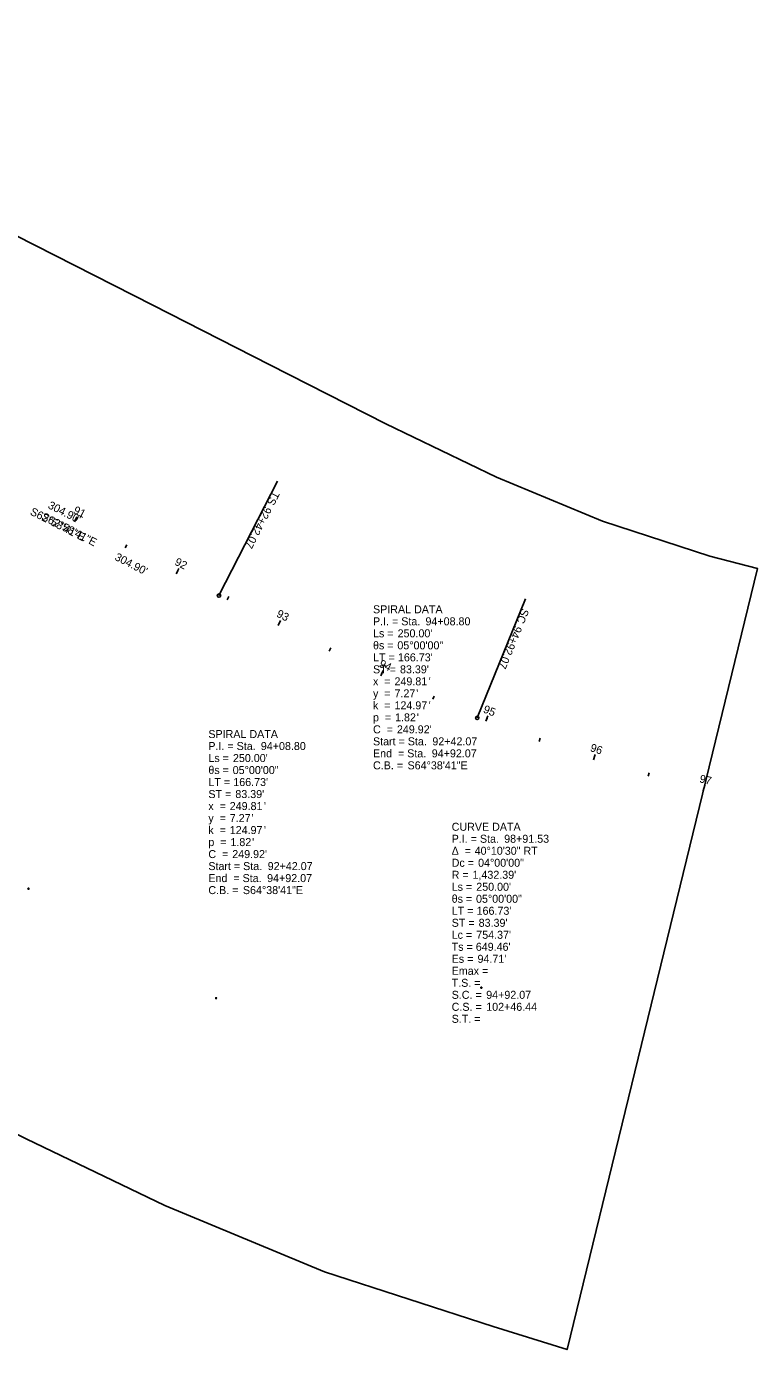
# Model space of a CAD drawing. Extents: x 1999328 to 2003366, y 252318 to 253988.
# Drawn here: x 2001707 to 2002347, y 252318 to 253475 of the extents above; entities that cross this region are included whole.
import ezdxf

# ---------------------------------------------------------------- set-up
doc = ezdxf.new("R2010")
doc.units = 0
for name, color, linetype in [('GE_P_Alignment_500_Stations', 7, 'Continuous'), ('GE_X_Alignment_100_Stations', 7, 'Continuous'), ('RW_X_Esmt_CH', 7, 'Continuous'), ('SC_Scratch3', 7, 'Continuous'), ('SV_X_Mon_Cells_Found', 7, 'Continuous'), ('TX_P_50', 7, 'Continuous'), ('TX_X_20', 7, 'Continuous'), ('TX_X_50', 7, 'Continuous')]:
    doc.layers.add(name, color=color, linetype=linetype)

msp = doc.modelspace()

# ---------------------------------------------------------------- linework, layer by layer
at = {"layer": 'GE_P_Alignment_500_Stations'}
for p, q in [((2001875.8, 252977.6), (2001927, 253077.8)), ((2001749.3, 253042.2), (2001751.6, 253046.6)), ((2001793.8, 253019.5), (2001795.2, 253022.1)), ((2001838.4, 252996.7), (2001840.6, 253001.2)), ((2001882.9, 252974), (2001884.3, 252976.7)), ((2002101.7, 252870.6), (2002143.9, 252974.9)), ((2001927.5, 252951.4), (2001929.7, 252955.9)), ((2001972.3, 252929.1), (2001973.6, 252931.8)), ((2002017.4, 252907.5), (2002019.5, 252912)), ((2002062.9, 252886.9), (2002064.1, 252889.7)), ((2002109.1, 252867.7), (2002110.9, 252872.3)), ((2002155.8, 252850), (2002156.8, 252852.8)), ((2002203.2, 252833.9), (2002204.7, 252838.7)), ((2002251.1, 252819.6), (2002251.9, 252822.5)), ((2002299.4, 252806.9), (2002300.6, 252811.7))]:
    msp.add_line(p, q, dxfattribs=at)
for centre in [(2001875.8, 252977.6), (2002101.7, 252870.6)]:
    msp.add_circle(centre, 1.5, dxfattribs=at)
at = {"layer": 'RW_X_Esmt_CH'}
msp.add_lwpolyline([(2001251, 253475.4), (2001057.7, 252727.4), (2001128.3, 252693.2), (2001227.4, 252644.1), (2001300.1, 252709.6), (2001397.4, 252660.4), (2001499.9, 252608.1), (2001602.3, 252555.9), (2001707.3, 252502.5), (2001828.3, 252444.1), (2001968.2, 252386.2), (2002115.7, 252338.2), (2002180.2, 252318.1), (2002346.8, 253001.2), (2002305.2, 253012.1), (2002211.1, 253042.7), (2002118.4, 253081.1), (2002021.8, 253127.8), (2001920.3, 253179.5), (2001817.9, 253231.7), (2001715.4, 253283.9), (2001610.7, 253336.9), (2001497.9, 253389.8), (2001376.4, 253437.5)], close=True, dxfattribs=at)
at = {"layer": 'SV_X_Mon_Cells_Found'}
for p, q in [((2001875.8, 252977.6), (2001927, 253077.8)), ((2002101.7, 252870.6), (2002143.9, 252974.9)), ((2002109.1, 252867.7), (2002110.2, 252870.4))]:
    msp.add_line(p, q, dxfattribs=at)
for centre in [(2001875.8, 252977.6), (2002101.7, 252870.6)]:
    msp.add_circle(centre, 1.5, dxfattribs=at)
at = {"layer": 'TX_P_50'}
for p, q in [((2001875.8, 252977.6), (2001927, 253077.8)), ((2001749.3, 253042.2), (2001750.7, 253044.8)), ((2001838.4, 252996.7), (2001839.7, 252999.4)), ((2002101.7, 252870.6), (2002143.9, 252974.9)), ((2001927.5, 252951.4), (2001928.8, 252954.1)), ((2002017.4, 252907.5), (2002018.6, 252910.2)), ((2002109.1, 252867.7), (2002110.9, 252872.3)), ((2002203.2, 252833.9), (2002204.1, 252836.8)), ((2002299.4, 252806.9), (2002300.1, 252809.8))]:
    msp.add_line(p, q, dxfattribs=at)
for centre in [(2001875.8, 252977.6), (2002101.7, 252870.6)]:
    msp.add_circle(centre, 1.5, dxfattribs=at)
at = {"layer": 'TX_X_20'}
for centre in [(2001709.2, 252721.3), (2001709.2, 252721.3), (2002105.2, 252634.6), (2002105.2, 252634.6), (2001873.3, 252625.5), (2001873.3, 252625.5)]:
    msp.add_circle(centre, 0.5, dxfattribs=at)

# ---------------------------------------------------------------- texts
at = {"layer": 'GE_P_Alignment_500_Stations'}
for s, rotation, p in [('TS', 242.9781, (2001922.9, 253069.6)), ('S62°58\'41"E', 332.9781, (2001719.8, 253044.4)), ('91', 332.9781, (2001747.7, 253050.1)), ('92+42.07', 242.9781, (2001916, 253056.1)), ("304.90'", 332.9781, (2001784, 253009.1)), ('92', 332.9781, (2001836.4, 253004.9)), ('93', 333.2466, (2001925.5, 252959.5)), ('SC', 247.9781, (2002140.7, 252966.9)), ('94+92.07', 247.9781, (2002134.6, 252951.7)), ('94', 334.9735, (2002015.2, 252915.6)), ('95', 338.2955, (2002106.3, 252875.6)), ('96', 342.2955, (2002199.9, 252841.7)), ('97', 346.2955, (2002295.5, 252814.4))]:
    msp.add_text(s, height=7, rotation=rotation, dxfattribs=at).set_placement(p)
at = {"layer": 'GE_X_Alignment_100_Stations'}
for s, p in [('SPIRAL DATA', (2002010.5, 252962.1)), ('P.I. = Sta. ', (2002010.5, 252951.6)), ('94+08.80', (2002056.4, 252951.6)), ('Ls = ', (2002010.5, 252941.1)), ("250.00'", (2002032, 252941.1)), ('θs = ', (2002010.5, 252930.6)), ('05°00\'00"', (2002031.8, 252930.6)), ('LT = ', (2002010.5, 252920.1)), ("166.73'", (2002032.3, 252920.1)), ('ST = ', (2002010.5, 252909.6)), ("83.39'", (2002034.1, 252909.6)), ('x  = ', (2002010.5, 252899.1)), ('249.81', (2002029.3, 252899.1)), ('7.27', (2002029.3, 252888.6)), ("'", (2002048.3, 252888.6)), ("'", (2002059.2, 252899.1)), ('y  = ', (2002010.5, 252888.6)), ('k  = ', (2002010.5, 252878.1)), ('124.97', (2002029.3, 252878.1)), ("'", (2002059.2, 252878.1)), ('p  = ', (2002010.5, 252867.6)), ('1.82', (2002029.8, 252867.6)), ("'", (2002048.8, 252867.6)), ('C  = ', (2002010.5, 252857.1)), ("249.92'", (2002031.4, 252857.1)), ('Start = Sta. ', (2002010.5, 252846.6)), ('92+42.07', (2002062.4, 252846.6)), ('End  = Sta. ', (2002010.5, 252836.1)), ('94+92.07', (2002061.9, 252836.1)), ('C.B. = ', (2002010.5, 252825.6)), ('S64°38\'41"E', (2002040.7, 252825.6))]:
    msp.add_text(s, height=7, dxfattribs=at).set_placement(p)
at = {"layer": 'SC_Scratch3'}
for s, p in [('SPIRAL DATA', (2002010.5, 252962.1)), ('P.I. = Sta. ', (2002010.5, 252951.6)), ('94+08.80', (2002056.4, 252951.6)), ('Ls = ', (2002010.5, 252941.1)), ("250.00'", (2002032, 252941.1)), ('θs = ', (2002010.5, 252930.6)), ('05°00\'00"', (2002031.8, 252930.6)), ('LT = ', (2002010.5, 252920.1)), ("166.73'", (2002032.3, 252920.1)), ('ST = ', (2002010.5, 252909.6)), ("83.39'", (2002034.1, 252909.6)), ('x  = ', (2002010.5, 252899.1)), ('249.81', (2002029.3, 252899.1)), ('7.27', (2002029.3, 252888.6)), ("'", (2002048.3, 252888.6)), ("'", (2002059.2, 252899.1)), ('y  = ', (2002010.5, 252888.6)), ('k  = ', (2002010.5, 252878.1)), ('124.97', (2002029.3, 252878.1)), ("'", (2002059.2, 252878.1)), ('p  = ', (2002010.5, 252867.6)), ('1.82', (2002029.8, 252867.6)), ("'", (2002048.8, 252867.6)), ('C  = ', (2002010.5, 252857.1)), ("249.92'", (2002031.4, 252857.1)), ('Start = Sta. ', (2002010.5, 252846.6)), ('92+42.07', (2002062.4, 252846.6)), ('End  = Sta. ', (2002010.5, 252836.1)), ('94+92.07', (2002061.9, 252836.1)), ('C.B. = ', (2002010.5, 252825.6)), ('S64°38\'41"E', (2002040.7, 252825.6))]:
    msp.add_text(s, height=7, dxfattribs=at).set_placement(p)
at = {"layer": 'SV_X_Mon_Cells_Found'}
for s, rotation, p in [("304.90'", 332.9781, (2001725.6, 253054.4)), ('TS', 242.9781, (2001922.9, 253069.6)), ('S62°58\'41"E', 332.9781, (2001709.9, 253048.8)), ('92+42.07', 242.9781, (2001916, 253056.1)), ('SC', 247.9781, (2002140.7, 252966.9)), ('94+92.07', 247.9781, (2002134.6, 252951.7))]:
    msp.add_text(s, height=7, rotation=rotation, dxfattribs=at).set_placement(p)
at = {"layer": 'TX_P_50'}
for s, rotation, p in [("304.90'", 332.9781, (2001725.6, 253054.4)), ('TS', 242.9781, (2001922.9, 253069.6)), ('S62°58\'41"E', 332.9781, (2001709.9, 253048.8)), ('92+42.07', 242.9781, (2001916, 253056.1)), ('SC', 247.9781, (2002140.7, 252966.9)), ('94+92.07', 247.9781, (2002134.6, 252951.7)), ('95', 338.2955, (2002106.3, 252875.6))]:
    msp.add_text(s, height=7, rotation=rotation, dxfattribs=at).set_placement(p)
at = {"layer": 'TX_X_50'}
for s, p in [('SPIRAL DATA', (2001866.5, 252853)), ('P.I. = Sta. ', (2001866.5, 252842.5)), ('94+08.80', (2001912.4, 252842.5)), ('Ls = ', (2001866.5, 252832)), ("250.00'", (2001888, 252832)), ('θs = ', (2001866.5, 252821.5)), ('05°00\'00"', (2001887.8, 252821.5)), ('LT = ', (2001866.5, 252811)), ("166.73'", (2001888.3, 252811)), ('ST = ', (2001866.5, 252800.5)), ("83.39'", (2001890.1, 252800.5)), ('x  = ', (2001866.5, 252790)), ('249.81', (2001885.2, 252790)), ("'", (2001915.1, 252790)), ('y  = ', (2001866.5, 252779.5)), ('7.27', (2001885.2, 252779.5)), ("'", (2001904.3, 252779.5)), ('k  = ', (2001866.5, 252769)), ('124.97', (2001885.2, 252769)), ("'", (2001915.1, 252769)), ('CURVE DATA', (2002079.3, 252771.9)), ('P.I. = Sta. ', (2002079.3, 252761.4)), ('98+91.53', (2002125.2, 252761.4)), ('p  = ', (2001866.5, 252758.5)), ('1.82', (2001885.8, 252758.5)), ("'", (2001904.8, 252758.5)), ('Δ  = ', (2002079.3, 252750.9)), ('40°10\'30" RT', (2002099.4, 252750.9)), ('Start = Sta. ', (2001866.5, 252737.5)), ('C  = ', (2001866.5, 252748)), ("249.92'", (2001887.4, 252748)), ('92+42.07', (2001918.4, 252737.5)), ('Dc = ', (2002079.3, 252740.4)), ('04°00\'00"', (2002102.4, 252740.4)), ('End  = Sta. ', (2001866.5, 252727)), ('94+92.07', (2001917.9, 252727)), ('R = ', (2002079.3, 252729.9)), ("1,432.39'", (2002097.5, 252729.9)), ('C.B. = ', (2001866.5, 252716.5)), ('S64°38\'41"E', (2001896.7, 252716.5)), ('Ls = ', (2002079.3, 252719.4)), ("250.00'", (2002100.8, 252719.4)), ('θs = ', (2002079.3, 252708.9)), ('05°00\'00"', (2002100.6, 252708.9)), ('LT = ', (2002079.3, 252698.4)), ("166.73'", (2002101.1, 252698.4)), ('ST = ', (2002079.3, 252687.9)), ("83.39'", (2002102.9, 252687.9)), ('Lc = ', (2002079.3, 252677.4)), ("754.37'", (2002100.8, 252677.4)), ('Ts = ', (2002079.3, 252666.9)), ("649.46'", (2002100.4, 252666.9)), ("94.71'", (2002101.9, 252656.4)), ('Es = ', (2002079.3, 252656.4)), ('Emax = ', (2002079.3, 252645.9)), ('T.S. = ', (2002079.3, 252635.4)), ('S.C. = ', (2002079.3, 252624.9)), ('94+92.07', (2002109.5, 252624.9)), ('C.S. = ', (2002079.3, 252614.4)), ('102+46.44', (2002109.5, 252614.4)), ('S.T. = ', (2002079.3, 252603.9))]:
    msp.add_text(s, height=7, dxfattribs=at).set_placement(p)

doc.saveas('drawing.dxf')
